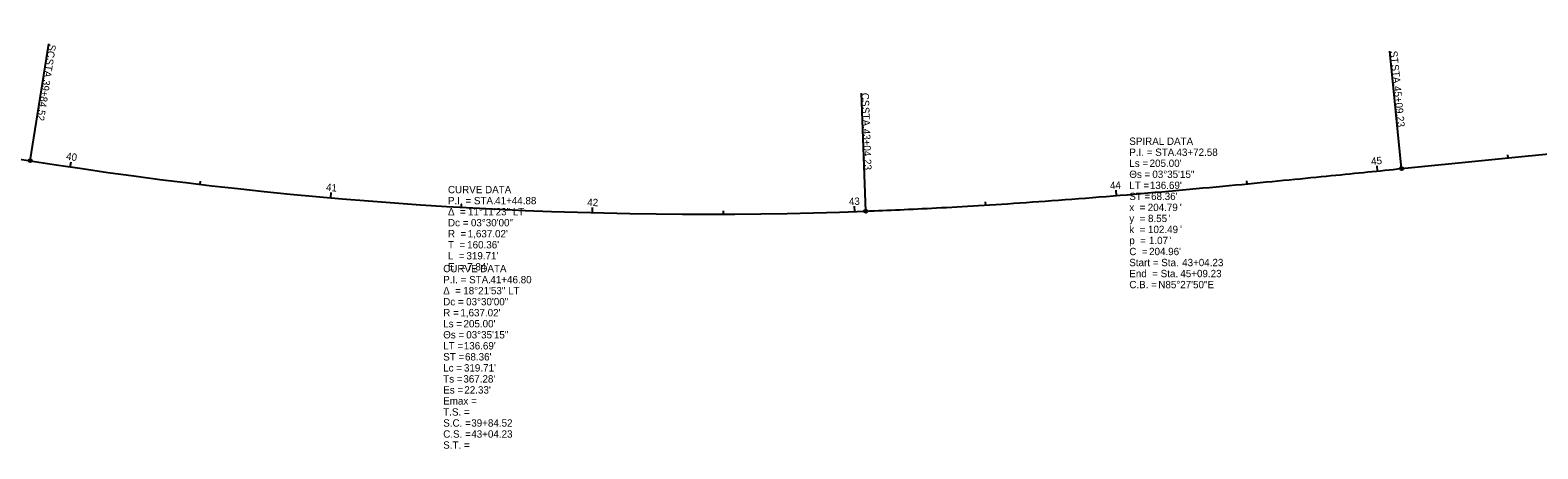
# Model space of a CAD drawing. Extents: x 198556 to 202876, y 391595 to 392065.
# Drawn here: x 199570 to 200145, y 391595 to 391755 of the extents above; entities that cross this region are included whole.
import ezdxf

# ---------------------------------------------------------------- set-up
doc = ezdxf.new("R2010")
doc.units = 0
for name, color, linetype in [('GE_X_Alignment', 7, 'Continuous'), ('GE_X_Alignment_100_Cardinal_Points', 7, 'Continuous'), ('GE_X_Alignment_100_Curve_Data', 7, 'Continuous'), ('GE_X_Alignment_100_Stations', 7, 'Continuous'), ('SC_Scratch3', 7, 'Continuous')]:
    doc.layers.add(name, color=color, linetype=linetype)

msp = doc.modelspace()

# ---------------------------------------------------------------- linework, layer by layer
at = {"layer": 'GE_X_Alignment'}
msp.add_line((200093.28, 391702), (200618.31, 391754.7), dxfattribs=at)
msp.add_arc((199827.71, 393321.66), 1637.02, 260.95473, 272.14444, dxfattribs=at)
for points in [[(199369.45, 391745.64), (199377.78, 391743.77), (199394.45, 391740.03), (199427.81, 391732.63), (199469.55, 391723.61), (199511.44, 391715.25), (199545.06, 391709.16), (199561.91, 391706.34), (199570.34, 391705)], [(199888.96, 391685.79), (199897.5, 391686.11), (199914.56, 391686.88), (199948.67, 391688.89), (199991.26, 391692.16), (200033.78, 391696.09), (200067.79, 391699.44), (200084.78, 391701.14), (200093.28, 391702)]]:
    msp.add_open_spline(points, degree=3, dxfattribs=at)
at = {"layer": 'GE_X_Alignment_100_Cardinal_Points'}
for p, q in [((199570.34, 391705), (199577.42, 391749.44)), ((200093.28, 391702), (200088.79, 391746.77)), ((199888.96, 391685.79), (199887.28, 391730.75))]:
    msp.add_line(p, q, dxfattribs=at)
for centre in [(199570.34, 391705), (200093.28, 391702), (199888.96, 391685.79)]:
    msp.add_circle(centre, 0.6, dxfattribs=at)
at = {"layer": 'GE_X_Alignment_100_Stations'}
for p, q in [((199585.64, 391702.64), (199585.94, 391704.61)), ((200084.1, 391701.07), (200083.9, 391703.06)), ((200133.85, 391706.07), (200133.73, 391707.26)), ((199635.2, 391696), (199635.34, 391697.19)), ((200034.34, 391696.18), (200034.23, 391697.38)), ((199684.93, 391690.88), (199685.11, 391692.87)), ((199984.54, 391691.73), (199984.38, 391693.72)), ((199734.8, 391687.28), (199734.87, 391688.48)), ((199784.75, 391685.2), (199784.81, 391687.2)), ((199834.75, 391684.65), (199834.74, 391685.85)), ((199884.74, 391685.63), (199884.67, 391687.63)), ((199934.68, 391688.09), (199934.6, 391689.29))]:
    msp.add_line(p, q, dxfattribs=at)
at = {"layer": 'SC_Scratch3'}
msp.add_arc((199827.71, 393321.66), 1637.02, 260.95473, 272.14444, dxfattribs=at)
for points in [[(199369.45, 391745.64), (199377.78, 391743.77), (199394.45, 391740.03), (199427.81, 391732.63), (199469.55, 391723.61), (199511.44, 391715.25), (199545.06, 391709.16), (199561.91, 391706.34), (199570.34, 391705)], [(199888.96, 391685.79), (199897.5, 391686.11), (199914.56, 391686.88), (199948.67, 391688.89), (199991.26, 391692.16), (200033.78, 391696.09), (200067.79, 391699.44), (200084.78, 391701.14), (200093.28, 391702)]]:
    msp.add_open_spline(points, degree=3, dxfattribs=at)

# ---------------------------------------------------------------- texts
at = {"layer": 'GE_X_Alignment_100_Cardinal_Points'}
for s, rotation, p in [('SC', 260.95473, (199577.46, 391749.47)), (' STA. ', 260.95473, (199576.77, 391745.17)), ('ST', 275.73194, (200088.84, 391746.68)), (' STA. ', 275.73194, (200089.25, 391742.59)), ('39+84.52', 260.95473, (199575.31, 391735.96)), ('CS', 272.14444, (199887.31, 391730.78)), ('45+09.23', 275.73194, (200090.18, 391733.31)), (' STA. ', 272.14444, (199887.48, 391726.43)), ('43+04.23', 272.14444, (199887.82, 391717.11))]:
    msp.add_text(s, height=2.8, rotation=rotation, dxfattribs=at).set_placement(p)
at = {"layer": 'GE_X_Alignment_100_Curve_Data'}
for s, p in [('SPIRAL DATA', (199989.44, 391711.02)), ('P.I. = STA. ', (199989.44, 391706.82)), ('43+72.58', (200007.43, 391706.82)), ('Ls = ', (199989.44, 391702.62)), ("205.00'", (199997.18, 391702.62)), ('Θs = ', (199989.44, 391698.42)), ('LT = ', (199989.44, 391694.22)), ("136.69'", (199997.28, 391694.22)), ('03°35\'15"', (199998.22, 391698.42)), ('CURVE DATA', (199729.65, 391692.59)), ('P.I. = STA. ', (199729.65, 391688.39)), ('41+44.88', (199747.64, 391688.39)), ('ST = ', (199989.44, 391690.02)), ("68.36'", (199997.74, 391690.02)), ('Δ  = ', (199729.65, 391684.19)), ('11°11\'23" LT', (199737.3, 391684.19)), ('x  = ', (199989.44, 391685.82)), ('204.79', (199996.47, 391685.82)), ("'", (200008.72, 391685.82)), ('Dc = ', (199729.65, 391679.99)), ('03°30\'00"', (199738.4, 391679.99)), ('y  = ', (199989.44, 391681.62)), ('k  = ', (199989.44, 391677.42)), ('8.55', (199996.57, 391681.62)), ('102.49', (199996.57, 391677.42)), ("'", (200004.35, 391681.62)), ("'", (200008.82, 391677.42)), ('T  = ', (199729.65, 391671.59)), ('R  = ', (199729.65, 391675.79)), ("160.36'", (199736.97, 391671.59)), ("1,637.02'", (199737.19, 391675.79)), ('p  = ', (199989.44, 391673.22)), ('1.07', (199996.92, 391673.22)), ("'", (200004.7, 391673.22)), ('L  = ', (199729.65, 391667.39)), ("319.71'", (199736.69, 391667.39)), ('Start = Sta. ', (199989.44, 391664.82)), ('C  = ', (199989.44, 391669.02)), ("204.96'", (199996.98, 391669.02)), ('43+04.23', (200009.59, 391664.82)), ('CURVE DATA', (199727.84, 391662.51)), ('E  = ', (199729.65, 391663.19)), ("7.84'", (199736.99, 391663.19)), ('End  = Sta. ', (199989.44, 391660.62)), ('45+09.23', (200008.9, 391660.62)), ('Δ  = ', (199727.84, 391654.11)), ('P.I. = STA. ', (199727.84, 391658.31)), ('18°21\'53" LT', (199735.48, 391654.11)), ('41+46.80', (199745.83, 391658.31)), ('C.B. = ', (199989.44, 391656.42)), ('N85°27\'50"E', (200000.5, 391656.42)), ('Dc = ', (199727.84, 391649.91)), ('03°30\'00"', (199736.58, 391649.91)), ('R = ', (199727.84, 391645.71)), ("1,637.02'", (199734.38, 391645.71)), ("205.00'", (199735.58, 391641.51)), ('Θs = ', (199727.84, 391637.31)), ('Ls = ', (199727.84, 391641.51)), ('03°35\'15"', (199736.62, 391637.31)), ('LT = ', (199727.84, 391633.11)), ("136.69'", (199735.69, 391633.11)), ('ST = ', (199727.84, 391628.91)), ('Lc = ', (199727.84, 391624.71)), ("319.71'", (199735.75, 391624.71)), ("68.36'", (199736.14, 391628.91)), ('Ts = ', (199727.84, 391620.51)), ("367.28'", (199735.52, 391620.51)), ('Es = ', (199727.84, 391616.31)), ("22.33'", (199735.89, 391616.31)), ('T.S. = ', (199727.84, 391607.91)), ('Emax = ', (199727.84, 391612.11)), ('S.C. = ', (199727.84, 391603.71)), ('39+84.52', (199738.54, 391603.71)), ('C.S. = ', (199727.84, 391599.51)), ('43+04.23', (199738.54, 391599.51)), ('S.T. = ', (199727.84, 391595.31))]:
    msp.add_text(s, height=2.8, dxfattribs=at).set_placement(p)
at = {"layer": 'GE_X_Alignment_100_Stations'}
for s, rotation, p in [('40', 351.49653, (199583.88, 391705.43)), ('45', 5.72468, (200081.77, 391703.35)), ('41', 354.99653, (199683.05, 391693.55)), ('44', 4.71351, (199982.18, 391694.05)), ('42', 358.49654, (199782.73, 391687.76)), ('43', 1.99654, (199882.57, 391688.06))]:
    msp.add_text(s, height=2.8, rotation=rotation, dxfattribs=at).set_placement(p)

doc.saveas('drawing.dxf')
